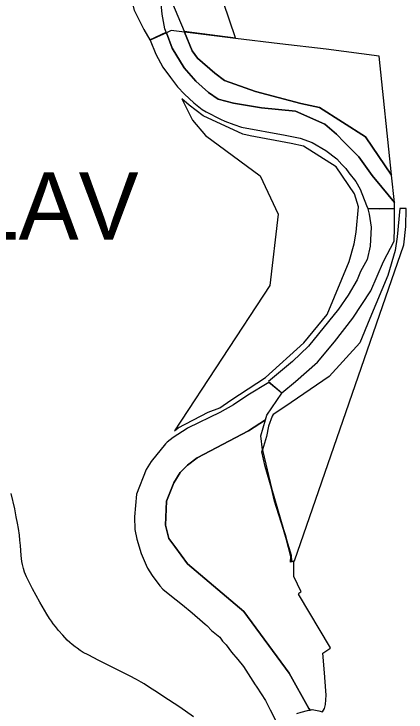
# Model space of a CAD drawing. Extents: x -759276 to -751881, y -1176141 to -1171097.
# Drawn here: x -756731 to -756064, y -1174246 to -1173060 of the extents above; entities that cross this region are included whole.
import ezdxf

# ---------------------------------------------------------------- set-up
doc = ezdxf.new("R2010")
doc.units = 0
for name, color, linetype in [('A_SILNICE', 7, 'Continuous'), ('A_USES', 7, 'Continuous'), ('AA_vyrezy', 7, 'Continuous')]:
    doc.layers.add(name, color=color, linetype=linetype)

msp = doc.modelspace()

# ---------------------------------------------------------------- linework, layer by layer
at = {"layer": 'A_SILNICE'}
msp.add_lwpolyline([(-756425.7, -1174254.2), (-756449.1, -1174238.3), (-756467.9, -1174225.7), (-756491.1, -1174210.2), (-756500.4, -1174204.4), (-756509.6, -1174198.4), (-756514.7, -1174195.4), (-756522.3, -1174191.1), (-756534.3, -1174184.9), (-756565.9, -1174168.8), (-756586.5, -1174158.6), (-756604.9, -1174149.3), (-756613, -1174144.9), (-756618.5, -1174141.5), (-756623.5, -1174138), (-756627, -1174135.4), (-756631.7, -1174131.4), (-756635.7, -1174128), (-756640.2, -1174123.9), (-756648, -1174115.8), (-756655.1, -1174107.6), (-756660.5, -1174100.9), (-756664, -1174096.2), (-756667.3, -1174091.6), (-756670.4, -1174087.1), (-756674.9, -1174079.8), (-756686.7, -1174059.5), (-756699.2, -1174036.7), (-756704.4, -1174026.9), (-756709.6, -1174016.3), (-756712.7, -1174008.8), (-756714.8, -1174002.5), (-756716.5, -1173995.6), (-756717.6, -1173990.4), (-756718.3, -1173985.3), (-756718.7, -1173980.4), (-756719.6, -1173963.2), (-756720.6, -1173954), (-756721.6, -1173945.6), (-756723.3, -1173934.3), (-756724.9, -1173925.3), (-756726.9, -1173914.5), (-756729.6, -1173900.9), (-756735.4, -1173874.6)], dxfattribs=at)
at = {"layer": 'A_USES'}
for p, q in [((-756441.7, -1173089.1), (-756354.4, -1173100.3)), ((-756499.8, -1173103.6), (-756472.2, -1173090.7)), ((-756462.1, -1173117.7), (-756471.8, -1173091.9)), ((-756441.4, -1173151.2), (-756462.1, -1173117.7)), ((-756421.8, -1173174.2), (-756441.4, -1173151.2)), ((-756464.7, -1173168), (-756452.8, -1173183.5)), ((-756452.8, -1173183.5), (-756441, -1173195.9)), ((-756441, -1173195.9), (-756425, -1173210.8)), ((-756357.7, -1173211.6), (-756383.9, -1173204.5)), ((-756425, -1173210.8), (-756410.7, -1173222.2)), ((-756242.9, -1173211.8), (-756211.5, -1173218.6)), ((-756410.7, -1173222.2), (-756404, -1173226)), ((-756404, -1173226), (-756380, -1173238.4)), ((-756380, -1173238.4), (-756372.1, -1173241.9)), ((-756372.1, -1173241.9), (-756357.2, -1173247.6)), ((-756169.5, -1173277.8), (-756182.5, -1173264)), ((-756169, -1173278.1), (-756144.3, -1173302.7)), ((-756121.7, -1173334.5), (-756144.3, -1173302.7)), ((-756105.4, -1173354.3), (-756121.7, -1173334.5)), ((-756089, -1173333.8), (-756089.1, -1173333)), ((-756084, -1173380.2), (-756089, -1173333.8)), ((-756142, -1173357.6), (-756131.5, -1173385.6)), ((-756105.4, -1173354.3), (-756084, -1173380.2)), ((-756084, -1173380.2), (-756105.4, -1173354.3)), ((-756084, -1173380.5), (-756084, -1173380.2)), ((-756109.7, -1173390.8), (-756129.4, -1173391)), ((-756129.4, -1173391), (-756127.1, -1173400.2)), ((-756084, -1173391), (-756109.7, -1173390.8)), ((-756154.5, -1173576.9), (-756124.2, -1173530.3)), ((-756252.3, -1173684.6), (-756214.9, -1173651.6)), ((-756333, -1173708), (-756357.4, -1173724.2)), ((-756357.4, -1173724.2), (-756381.1, -1173737.2)), ((-756303.4, -1173749.4), (-756301.1, -1173741.5)), ((-756290.4, -1173740.8), (-756292.1, -1173743.7)), ((-756436.6, -1173764.3), (-756460.3, -1173779.5)), ((-756457.9, -1173768.1), (-756451.5, -1173763.4)), ((-756301.8, -1173777.8), (-756308.2, -1173800.4)), ((-756473.3, -1173790.3), (-756497.6, -1173820.5)), ((-756309.3, -1173804.3), (-756308.2, -1173800.4)), ((-756287.9, -1173887.8), (-756293.1, -1173865.9)), ((-756293.1, -1173865.9), (-756272.5, -1173936)), ((-756471.3, -1173888.1), (-756473.4, -1173928.7)), ((-756272.5, -1173936), (-756287.9, -1173887.8)), ((-756473.4, -1173928.7), (-756467.8, -1173951.3)), ((-756267.4, -1173953.6), (-756272.5, -1173936)), ((-756272.5, -1173936), (-756269.4, -1173946)), ((-756521.7, -1173952.4), (-756514.7, -1173977)), ((-756467.8, -1173951.3), (-756457.1, -1173964.9)), ((-756269.4, -1173946), (-756267.4, -1173953.6)), ((-756267.4, -1173953.6), (-756259.8, -1173979.7)), ((-756457.1, -1173964.9), (-756435.8, -1173994.2)), ((-756514.7, -1173977), (-756504.6, -1174000.7)), ((-756255, -1173989.4), (-756254.1, -1173989.2)), ((-756504.6, -1174000.7), (-756504, -1174001.6)), ((-756504, -1174001.6), (-756495.8, -1174014.4)), ((-756435.8, -1173994.2), (-756340, -1174075.4)), ((-756495.8, -1174014.4), (-756482.8, -1174031.7)), ((-756482.8, -1174031.7), (-756477.6, -1174037.4)), ((-756477.6, -1174037.4), (-756465.9, -1174047.3)), ((-756340, -1174075.4), (-756262.9, -1174180.1)), ((-756227.5, -1174242.9), (-756223.6, -1174242.2)), ((-756223.6, -1174242.2), (-756212.8, -1174244.1)), ((-756212.8, -1174244.1), (-756206.5, -1174246.2))]:
    msp.add_line(p, q, dxfattribs=at)
for points in [[(-756481, -1172835.1), (-756488.6, -1172848.8), (-756498.3, -1172896.3), (-756505.2, -1172926.3), (-756511.2, -1172953.9), (-756516.4, -1172973.5), (-756526.7, -1173002.4), (-756531.2, -1173035.3), (-756526.6, -1173053.4), (-756509.8, -1173086.2), (-756499.8, -1173103.6)], [(-756420.9, -1172852), (-756429, -1172868.2), (-756438.9, -1172912), (-756465.7, -1173014.2), (-756467.4, -1173026.5), (-756452.1, -1173063.4), (-756441.7, -1173089.1)], [(-756354.4, -1173100.3), (-756374.5, -1173040.3), (-756382.1, -1172950.3), (-756351, -1172860.5)], [(-756472.2, -1173090.7), (-756474.4, -1173085), (-756479.1, -1173060.1), (-756481.6, -1173030)], [(-756441, -1173090.9), (-756463.6, -1173088.2), (-756471.8, -1173091.9), (-756462.1, -1173117.7)], [(-756471.8, -1173091.9), (-756499.3, -1173104.5), (-756489.9, -1173128.1), (-756477.7, -1173150.4), (-756464.7, -1173168)], [(-756089, -1173333.8), (-756133, -1173268.6), (-756211.5, -1173218.6), (-756242.9, -1173211.8), (-756320.1, -1173191.7), (-756373, -1173172.7), (-756389.1, -1173160.5), (-756418.8, -1173135.1), (-756428.1, -1173122.7), (-756441, -1173090.9)], [(-756354, -1173101.4), (-756435.7, -1173091.5), (-756441, -1173090.9)], [(-756441, -1173090.9), (-756428.1, -1173122.7), (-756418.8, -1173135.1), (-756389.1, -1173160.5), (-756373, -1173172.7), (-756320.1, -1173191.7), (-756242.9, -1173211.8)], [(-756200.3, -1173119.9), (-756278.6, -1173110.5), (-756354, -1173101.4)], [(-756462.1, -1173117.7), (-756441.4, -1173151.2), (-756421.8, -1173174.2), (-756400.2, -1173193.5)], [(-756089.1, -1173333), (-756109.7, -1173131.5), (-756200.3, -1173119.9)], [(-756383.9, -1173204.5), (-756400.2, -1173193.5), (-756421.8, -1173174.2)], [(-756400.2, -1173193.5), (-756383.9, -1173204.5), (-756357.7, -1173211.6), (-756310.1, -1173219.4), (-756252.4, -1173225), (-756202.3, -1173247), (-756182.5, -1173264), (-756169.5, -1173277.8), (-756169, -1173278.1)], [(-756445.6, -1173204.3), (-756427.6, -1173240.4), (-756405.4, -1173266.6), (-756312.1, -1173335.1), (-756281.7, -1173400.2), (-756295.8, -1173521.1), (-756457.9, -1173768.1)], [(-756451.5, -1173763.4), (-756400.5, -1173736.6), (-756380.9, -1173729.4), (-756362, -1173716.5), (-756303.5, -1173677.5), (-756237.9, -1173619), (-756198.5, -1173570.9), (-756161.2, -1173480.5), (-756152.2, -1173450.4), (-756148.9, -1173430.8), (-756145, -1173387.9), (-756151.9, -1173365.7), (-756182.9, -1173319.8), (-756238.6, -1173284.4), (-756259.6, -1173279.8), (-756329.2, -1173267), (-756341.7, -1173264.4), (-756409.1, -1173233.1), (-756433, -1173215), (-756445.6, -1173204.3)], [(-756182.5, -1173264), (-756202.3, -1173247), (-756252.4, -1173225), (-756310.1, -1173219.4), (-756357.7, -1173211.6)], [(-756211.5, -1173218.6), (-756133, -1173268.6), (-756089, -1173333.8)], [(-756357.2, -1173247.6), (-756344, -1173252), (-756270, -1173265.6), (-756244.5, -1173270.9), (-756224.1, -1173278.5), (-756200.6, -1173291.8), (-756181.9, -1173305.8), (-756173.5, -1173315.8)], [(-756144.3, -1173302.7), (-756169, -1173278.1), (-756169.5, -1173277.8)], [(-756144.3, -1173302.7), (-756121.7, -1173334.5), (-756105.4, -1173354.3)], [(-756173.5, -1173315.8), (-756166.9, -1173322.3), (-756161.8, -1173329.7)], [(-756161.8, -1173329.7), (-756149.9, -1173344.8), (-756142, -1173357.6)], [(-756131.5, -1173385.6), (-756129.3, -1173390.6), (-756109.7, -1173390.8)], [(-756109.7, -1173390.8), (-756101.7, -1173390.7), (-756084, -1173390.5), (-756084, -1173380.5)], [(-756075, -1173390.4), (-756079.4, -1173438.7), (-756082.5, -1173461.8), (-756095.1, -1173504.1), (-756125.8, -1173577.4), (-756143, -1173619), (-756195.1, -1173676), (-756270.2, -1173727.4), (-756290.4, -1173740.8)], [(-756254.1, -1173989.2), (-756067.8, -1173452.3), (-756064.9, -1173421.2), (-756064.3, -1173390.3), (-756073.8, -1173390.4), (-756075, -1173390.4)], [(-756124.2, -1173530.3), (-756102.4, -1173480.4), (-756084.5, -1173446.1), (-756084, -1173422.6), (-756084, -1173404.7), (-756084, -1173391)], [(-756127.1, -1173400.2), (-756123.5, -1173422.4), (-756125, -1173454.7)], [(-756125, -1173454.7), (-756130.2, -1173477.3), (-756141.9, -1173497.4), (-756147.3, -1173511.9), (-756162.8, -1173537.6), (-756179.2, -1173561.6), (-756230.2, -1173624.2), (-756257.1, -1173650.4), (-756298.1, -1173684.7), (-756275.6, -1173703.9), (-756252.3, -1173684.6)], [(-756214.9, -1173651.6), (-756186, -1173617.3), (-756154.5, -1173576.9)], [(-756301.1, -1173741.5), (-756275.3, -1173704.5), (-756297.8, -1173686), (-756333, -1173708)], [(-756381.1, -1173737.2), (-756434.7, -1173763.2), (-756436.6, -1173764.3)], [(-756227.5, -1174242.9), (-756229.3, -1174240.5), (-756262.9, -1174180.1), (-756340, -1174075.4), (-756435.8, -1173994.2), (-756457.1, -1173964.9), (-756467.8, -1173951.3), (-756473.4, -1173928.7), (-756471.3, -1173888.1), (-756459, -1173856.7), (-756448.1, -1173839.4), (-756435.9, -1173826.5), (-756419.5, -1173814.4), (-756332, -1173768.4), (-756303.4, -1173749.4)], [(-756303.4, -1173749.4), (-756332, -1173768.4), (-756419.5, -1173814.4), (-756435.9, -1173826.5), (-756448.1, -1173839.4)], [(-756308.2, -1173800.4), (-756311.1, -1173776.6), (-756303.4, -1173749.4)], [(-756292.1, -1173743.7), (-756298.3, -1173760.4), (-756301.8, -1173777.8)], [(-756460.3, -1173779.5), (-756470.5, -1173787.4), (-756473.3, -1173790.3)], [(-756308.2, -1173800.4), (-756307.8, -1173803.7), (-756293.1, -1173865.9)], [(-756293.1, -1173865.9), (-756303.9, -1173828.7), (-756309.3, -1173804.3)], [(-756497.6, -1173820.5), (-756506.2, -1173834.1), (-756522.5, -1173876.1), (-756526.1, -1173914.7), (-756525.2, -1173936.2), (-756521.7, -1173952.4)], [(-756448.1, -1173839.4), (-756459, -1173856.7), (-756471.3, -1173888.1)], [(-756242.6, -1174041.9), (-756254.8, -1174016.1), (-756254.8, -1173990.3), (-756260.8, -1173991.7), (-756260.1, -1173981.7), (-756267.4, -1173953.6)], [(-756259.8, -1173979.7), (-756259.2, -1173990.4), (-756255, -1173989.4)], [(-756465.9, -1174047.3), (-756444.5, -1174064.3), (-756428.1, -1174077.7), (-756410.5, -1174092.9)], [(-756193.6, -1174138.4), (-756192.6, -1174137.2), (-756246.9, -1174045.9), (-756246.2, -1174045.4)], [(-756246.2, -1174045.4), (-756246.7, -1174044.5), (-756244.7, -1174043.2), (-756242.6, -1174041.9)], [(-756410.5, -1174092.9), (-756405.7, -1174096.9), (-756403.1, -1174099.4)], [(-756403.1, -1174099.4), (-756402.5, -1174099.9), (-756394.9, -1174107.5)], [(-756394.9, -1174107.5), (-756381.1, -1174119.1), (-756376.3, -1174125.7)], [(-756376.3, -1174125.7), (-756369.9, -1174131.9), (-756360.9, -1174144.3)], [(-756360.9, -1174144.3), (-756350.2, -1174156.8), (-756340.4, -1174169.1), (-756320.6, -1174199.8)], [(-756202.6, -1174186.3), (-756205.5, -1174146.1), (-756193.6, -1174138.4)], [(-756262.9, -1174180.1), (-756229.3, -1174240.5), (-756227.5, -1174242.9)], [(-756201.3, -1174233.6), (-756199.9, -1174217.9), (-756202.5, -1174187.5), (-756202.6, -1174186.3)], [(-756320.6, -1174199.8), (-756319, -1174202.1), (-756317.8, -1174204.3)], [(-756317.8, -1174204.3), (-756303.3, -1174226.8), (-756295.2, -1174242.6), (-756283.8, -1174264.9)], [(-756206.5, -1174246.2), (-756202.8, -1174240.5), (-756201.3, -1174233.6)], [(-756250.2, -1174249), (-756250.1, -1174248.9), (-756242.6, -1174246.6), (-756231.7, -1174243.8), (-756227.5, -1174242.9)]]:
    msp.add_lwpolyline(points, dxfattribs=at)

# ---------------------------------------------------------------- texts
at = {"layer": 'AA_vyrezy'}
msp.add_text('PLAV', height=114.37, rotation=360, dxfattribs=at).set_placement((-756910, -1173443.2))

doc.saveas('drawing.dxf')
